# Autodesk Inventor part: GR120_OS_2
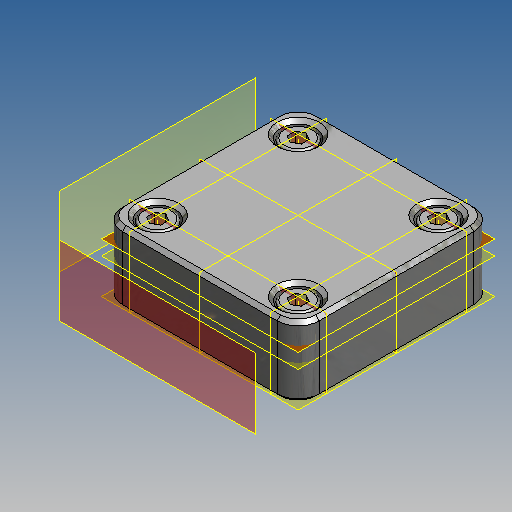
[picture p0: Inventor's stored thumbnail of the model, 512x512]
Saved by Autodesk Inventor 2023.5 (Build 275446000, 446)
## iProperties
Part Number: GR120_OS_2
Material: Allgemein
Document SubType Name: Modellieren
Designer: WH
Appearance: Vorgabe
Author: WH
NB: GR120-OS_2
NN: GR120-OS
NBSYN: $CNSORDERNO._2
LINA: GR120-OS_2
CATALOG: GIGAGER
CNSORDERNO: GR120-OS
SCS: GR120
SUPPLIER: SAINI
ARTICLENO: GR120-OS_2
BOMINFO: GR120-OS_2
CREATOR: CADENAS GmbH
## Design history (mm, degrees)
feature "GR120_OS_2"
node "A_1"
node "A_2"
node "A_3"
node "A_4"
node "A_5"
node "A_6"
node "A_7"
node "A_8"
node "A_9"
node "2_ZAXS"
node "22_ZAXS"
node "RIGHT"
node "TOP"
node "FRONT"
node "DTM1"
node "DTM2"
node "DTM3"
node "DTM4"
node "DTM5"
node "DTM6"
node "DTM7"
node "DTM8"
node "DTM9"
node "DTM10"
node "DTM11"
node "DTM12"
node "DTM13"
node "DTM14"
node "DTM15"
node "DTM16"
node "DTM17"
node "DTM18"
node "DTM19"
node "DTM20"
node "DTM21"
node "DTM22"
node "DTM23"
node "DTM24"
node "DTM25"
node "DTM26"
node "DTM27"
node "2_XPLN"
node "2_YPLN"
node "2_ZPLN"
node "22_XPLN"
node "22_YPLN"
node "22_ZPLN"
node "Volumenkörper1"
node "Volumenkörper"
node "Flächenkörper"
